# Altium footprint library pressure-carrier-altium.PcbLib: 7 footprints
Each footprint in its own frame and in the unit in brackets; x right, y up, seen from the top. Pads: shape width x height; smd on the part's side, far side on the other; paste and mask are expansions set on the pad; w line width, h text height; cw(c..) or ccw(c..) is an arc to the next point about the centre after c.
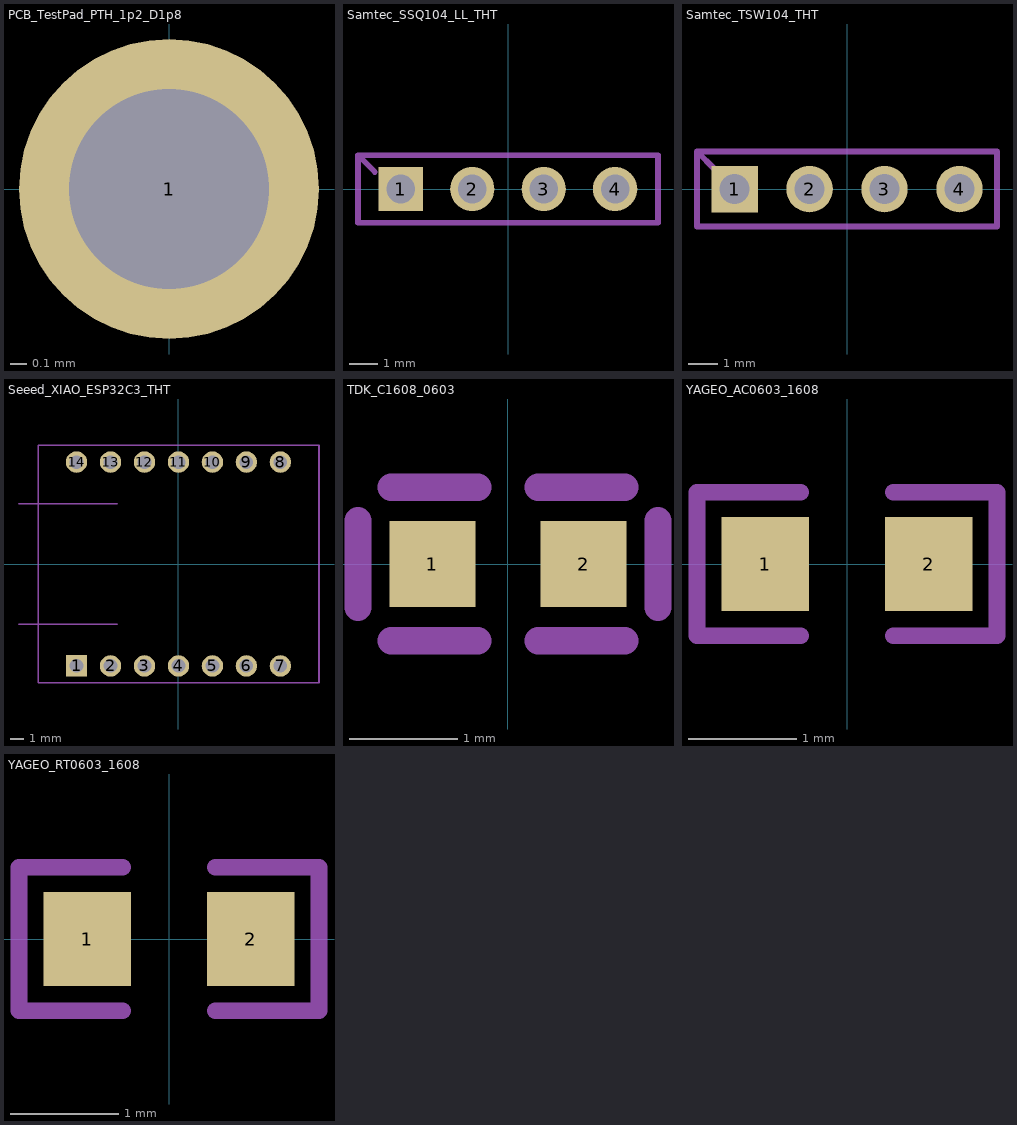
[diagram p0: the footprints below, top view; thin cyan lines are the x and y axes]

## PCB_TestPad_PTH_1p2_D1p8 [mil] "PCB_TestPad_PTH_1p2_D1p8"
pads (1):
  round 70.87 / inner round 0 / far side round 70.87 hole 47.24: 1(0,0)

## Samtec_SSQ104_LL_THT [mil] "Samtec_SSQ104_LL_THT"
pads (4):
  rect 62x62 / inner round 0 / far side rect 62x62 hole 40.16: 1(-150,0)
  round 62 / inner round 0 / far side round 62 hole 40.16: 2(-50,0) 3(50,0) 4(150,0)
Mechanical 7:
  lines w7.99: -210.04,-47.44 210.04,-47.44
  lines w8: -210.04,-47.44 -210.04,47.44 ; -186.42,23.82 -210.04,47.44 ; 210.04,-47.44 210.04,47.44 -210.04,47.44

## Samtec_TSW104_THT [mil] "Samtec_TSW104_THT"
pads (4):
  rect 62x62 / inner round 0 / far side rect 62x62 hole 40.16: 1(-150,0)
  round 62 / inner round 0 / far side round 62 hole 40.16: 2(-50,0) 3(50,0) 4(150,0)
Mechanical 7:
  lines w7.99: -200,-50 200,-50
  lines w8: -200,-50 -200,50 ; -176.38,26.38 -200,50 ; 200,-50 200,50 -200,50

## Seeed_XIAO_ESP32C3_THT [mm] "Seeed_XIAO_ESP32C3_THT"
pads (14):
  rect 1.6x1.6 / inner round 0 / far side rect 1.6x1.6 hole 1.02: 1(-7.62,-7.62)
  round 1.6 / inner round 0 / far side round 1.6 hole 1.02: 2(-5.08,-7.62) 3(-2.54,-7.62) 4(0,-7.62) 5(2.54,-7.62) 6(5.08,-7.62) 7(7.62,-7.62) 8(7.62,7.62) 9(5.08,7.62) 10(2.54,7.62) 11(0,7.62) 12(-2.54,7.62) 13(-5.08,7.62) 14(-7.62,7.62)
Mechanical 7:
  lines w0.127: -11.923,-4.501 -4.572,-4.501 ; -11.923,4.501 -4.572,4.501 ; -10.493,-8.89 -10.493,8.89 10.508,8.89 10.508,-8.89 -10.493,-8.89

## TDK_C1608_0603 [mm] "TDK_C1608_0603"
pads (2):
  rect 0.8x0.8 smd: 1(-0.7,0) 2(0.7,0)
Mechanical 7:
  lines w0.254: -1.39,-0.4 -1.39,0.4 ; -1.08,-0.71 -0.28,-0.71 ; -1.08,0.71 -0.28,0.71 ; 0.28,-0.71 1.08,-0.71 ; 0.28,0.71 1.08,0.71 ; 1.39,-0.4 1.39,0.4

## YAGEO_AC0603_1608 [mil] "YAGEO_AC0603_1608"
pads (2):
  rect 31.75x34.02 smd: 1(-29.66,0) 2(29.66,0)
Mechanical 7:
  lines w6: -16.78,-26.01 -54.53,-26.01 -54.53,26.01 -16.78,26.01 ; 16.78,-26.01 54.53,-26.01 54.53,26.01 16.78,26.01

## YAGEO_RT0603_1608 [mil] "YAGEO_RT0603_1608"
pads (2):
  rect 31.75x34.02 smd: 1(-29.66,0) 2(29.66,0)
Mechanical 7:
  lines w6: -16.78,-26.01 -54.53,-26.01 -54.53,26.01 -16.78,26.01 ; 16.78,-26.01 54.53,-26.01 54.53,26.01 16.78,26.01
